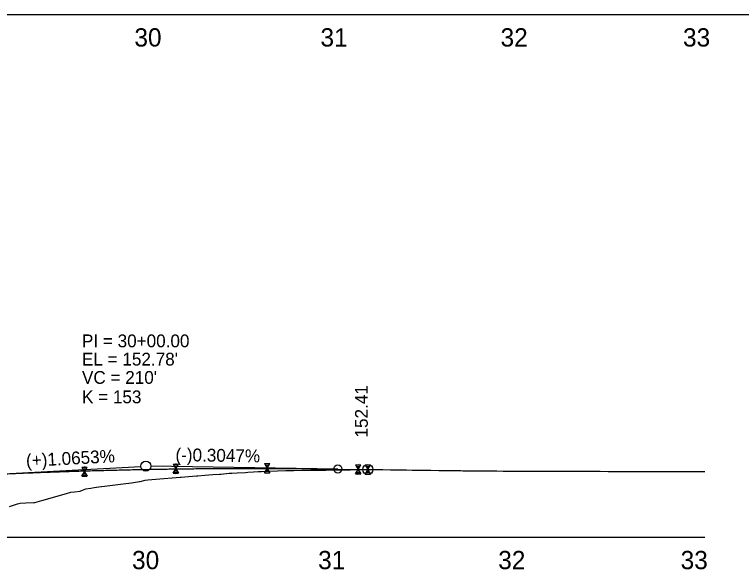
# Model space of a CAD drawing. Extents: x 573468 to 580768, y -57414 to -51768.
# Drawn here: x 575698.2 to 576096, y -53708.9 to -53405.3 of the extents above; entities that cross this region are included whole.
import ezdxf

# ---------------------------------------------------------------- set-up
doc = ezdxf.new("R2010")
doc.units = 0
for name, color, linetype in [('Exist Profile Cell', 7, 'Continuous'), ('Exist Vertical Profile Ground Line', 7, 'Continuous'), ('Exist Vertical Profile Horizontal Axis Label Major', 7, 'Continuous'), ('Pattern 2', 7, 'Continuous'), ('Prop Vertical Profile Curve Label', 7, 'Continuous'), ('Prop Vertical Profile Grade', 7, 'Continuous'), ('Prop Vertical Profile Grade Label', 7, 'Continuous'), ('Prop VPI Label', 7, 'Continuous')]:
    doc.layers.add(name, color=color, linetype=linetype)

msp = doc.modelspace()

# ---------------------------------------------------------------- linework, layer by layer
at = {"layer": 'Exist Profile Cell'}
for p, q in [((573502.62, -53405.32), (576177.52, -53405.32)), ((573531.99, -53691.24), (576075.95, -53691.24))]:
    msp.add_line(p, q, dxfattribs=at)
at = {"layer": 'Exist Vertical Profile Ground Line'}
for points in [[(575731.04, -53666.41), (575734.14, -53665.98), (575735.49, -53665.44), (575737.3, -53664.72), (575739.95, -53664.35), (575741.73, -53664.09), (575744.4, -53663.76), (575748.85, -53663.21), (575753.3, -53662.64), (575757.75, -53662.05), (575762.2, -53661.44), (575766.66, -53660.82), (575766.98, -53660.78), (575769.63, -53660.04), (575771.11, -53659.92), (575775.56, -53659.55), (575780.01, -53659.18), (575784.46, -53658.81), (575788.91, -53658.44), (575789.46, -53658.39), (575793.37, -53658.06), (575797.82, -53657.68), (575798.46, -53657.63), (575802.27, -53657.35), (575806.72, -53657.02), (575810.3, -53656.75), (575811.17, -53656.67), (575815.62, -53656.26), (575817.05, -53656.13), (575820.08, -53655.98), (575824.53, -53655.77), (575825.92, -53655.7), (575828.98, -53655.5), (575831.55, -53655.32), (575833.39, -53655.25), (575837.8, -53655.07), (575842.21, -53654.89), (575846.62, -53654.72), (575847.02, -53654.71), (575847.81, -53654.7), (575851.03, -53654.67), (575855.44, -53654.62), (575859.85, -53654.57), (575864.26, -53654.52), (575868.67, -53654.48), (575870.5, -53654.46), (575872.53, -53654.44), (575873.08, -53654.43), (575875.13, -53654.41), (575877.49, -53654.38), (575881.9, -53654.32), (575886.31, -53654.26), (575890.72, -53654.2), (575891.57, -53654.19), (575895.13, -53654.24), (575899.09, -53654.29), (575899.8, -53654.29), (575903.95, -53654.34), (575908.36, -53654.4), (575909.99, -53654.42), (575912.77, -53654.45), (575915.87, -53654.49), (575917.18, -53654.51), (575921.59, -53654.57), (575926, -53654.63), (575930.41, -53654.69), (575934.82, -53654.75), (575938.81, -53654.8), (575939.23, -53654.8), (575942.49, -53654.83), (575943.64, -53654.85), (575947.11, -53654.89), (575948.05, -53654.9), (575952.46, -53654.93), (575956.87, -53654.97), (575961.28, -53655), (575962.07, -53655.01), (575965.69, -53655.04), (575970.1, -53655.07), (575974.51, -53655.1), (575976.49, -53655.11), (575978.93, -53655.12), (575982.38, -53655.13), (575983.34, -53655.14), (575984.86, -53655.15), (575987.75, -53655.16), (575992.16, -53655.17), (575996.57, -53655.18), (576000.98, -53655.19), (576005.39, -53655.2), (576005.84, -53655.2), (576009.8, -53655.2), (576014.21, -53655.19), (576014.82, -53655.19), (576015.79, -53655.19), (576018.62, -53655.2), (576023.13, -53655.23), (576027.44, -53655.24), (576029.08, -53655.24), (576031.85, -53655.25), (576036.26, -53655.27)], [(576036.26, -53655.27), (576040.67, -53655.29), (576045.08, -53655.3), (576049.49, -53655.32), (576052.49, -53655.33), (576053.9, -53655.34), (576056.55, -53655.35), (576058.31, -53655.34), (576062.72, -53655.33), (576065.23, -53655.33), (576067.13, -53655.33), (576068.52, -53655.33), (576071.54, -53655.32), (576075.95, -53655.3)], [(575695.43, -53674.53), (575699.88, -53673.04), (575701.23, -53672.58), (575704.33, -53672.43), (575708.78, -53672.2), (575709.34, -53672.17), (575713.24, -53671.11), (575717.69, -53669.88), (575722.14, -53668.64), (575726.59, -53667.37), (575728.98, -53666.69), (575731.04, -53666.41)]]:
    msp.add_lwpolyline(points, dxfattribs=at)
at = {"layer": 'Pattern 2'}
for p, q in [((575735.1, -53652.94), (575738.03, -53652.94)), ((575735.1, -53652.94), (575736.57, -53655.44)), ((575736.57, -53655.44), (575738.03, -53652.94)), ((575785.03, -53651.29), (575787.96, -53651.29)), ((575785.03, -53651.29), (575786.5, -53653.79)), ((575785.52, -53652.13), (575787.47, -53652.13)), ((575786.01, -53652.96), (575786.99, -53652.96)), ((575786.5, -53653.79), (575787.96, -53651.29)), ((575834.99, -53650.99), (575837.92, -53650.99)), ((575834.99, -53650.99), (575836.46, -53653.49)), ((575835.48, -53651.83), (575837.43, -53651.83)), ((575835.97, -53652.66), (575836.95, -53652.66)), ((575836.46, -53653.49), (575837.92, -53650.99)), ((575884.88, -53651.64), (575887.81, -53651.64)), ((575884.88, -53651.64), (575886.35, -53654.14)), ((575885.37, -53652.48), (575887.32, -53652.48)), ((575885.86, -53653.31), (575886.84, -53653.31)), ((575886.35, -53654.14), (575887.81, -53651.64)), ((575890.09, -53651.69), (575893.02, -53651.69)), ((575890.09, -53651.69), (575891.56, -53654.19)), ((575890.58, -53652.53), (575892.53, -53652.53)), ((575891.07, -53653.36), (575892.05, -53653.36)), ((575891.56, -53654.19), (575893.02, -53651.69)), ((575735.1, -53657.94), (575736.57, -53655.44)), ((575735.59, -53653.78), (575737.54, -53653.78)), ((575735.59, -53657.11), (575737.54, -53657.11)), ((575736.08, -53654.61), (575737.06, -53654.61)), ((575736.08, -53656.28), (575737.06, -53656.28)), ((575736.57, -53655.44), (575738.03, -53657.94)), ((575785.03, -53656.29), (575786.5, -53653.79)), ((575785.03, -53656.29), (575787.96, -53656.29)), ((575785.52, -53655.46), (575787.47, -53655.46)), ((575786.01, -53654.63), (575786.99, -53654.63)), ((575786.5, -53653.79), (575787.96, -53656.29)), ((575834.99, -53655.99), (575836.46, -53653.49)), ((575834.99, -53655.99), (575837.92, -53655.99)), ((575835.48, -53655.16), (575837.43, -53655.16)), ((575835.97, -53654.33), (575836.95, -53654.33)), ((575836.46, -53653.49), (575837.92, -53655.99)), ((575884.88, -53656.64), (575886.35, -53654.14)), ((575884.88, -53656.64), (575887.81, -53656.64)), ((575885.37, -53655.81), (575887.32, -53655.81)), ((575885.86, -53654.98), (575886.84, -53654.98)), ((575886.35, -53654.14), (575887.81, -53656.64)), ((575890.09, -53656.69), (575891.56, -53654.19)), ((575890.09, -53656.69), (575893.02, -53656.69)), ((575890.58, -53655.86), (575892.53, -53655.86)), ((575891.07, -53655.03), (575892.05, -53655.03)), ((575891.56, -53654.19), (575893.02, -53656.69)), ((575735.1, -53657.94), (575738.03, -53657.94))]:
    msp.add_line(p, q, dxfattribs=at)
at = {"layer": 'Prop Vertical Profile Curve Label'}
msp.add_circle((575875.13, -53653.94), 2.25, dxfattribs=at)
at = {"layer": 'Prop Vertical Profile Grade'}
msp.add_line((575875.13, -53653.94), (575891.56, -53654.19), dxfattribs=at)
msp.add_spline([(575665.13, -53657.94), (575669.33, -53657.72), (575673.53, -53657.5), (575677.73, -53657.29), (575681.93, -53657.09), (575686.13, -53656.89), (575690.33, -53656.7), (575694.53, -53656.51), (575698.73, -53656.33), (575702.93, -53656.16), (575707.13, -53655.99), (575711.33, -53655.82), (575715.53, -53655.67), (575719.73, -53655.51), (575723.93, -53655.37), (575728.13, -53655.23), (575732.33, -53655.09), (575736.53, -53654.96), (575740.73, -53654.84), (575744.93, -53654.72), (575749.13, -53654.61), (575753.33, -53654.51), (575757.53, -53654.41), (575761.73, -53654.31), (575765.93, -53654.22), (575770.13, -53654.14), (575774.33, -53654.06), (575778.53, -53653.99), (575782.73, -53653.93), (575786.93, -53653.87), (575791.13, -53653.81), (575795.33, -53653.77), (575799.53, -53653.72), (575803.73, -53653.69), (575807.93, -53653.66), (575812.13, -53653.63), (575816.33, -53653.61), (575820.53, -53653.6), (575824.73, -53653.59), (575828.93, -53653.59), (575833.13, -53653.59), (575837.33, -53653.6), (575841.53, -53653.62), (575845.73, -53653.64), (575849.93, -53653.66), (575854.13, -53653.7), (575858.33, -53653.73), (575862.53, -53653.78), (575866.73, -53653.83), (575870.93, -53653.88), (575875.13, -53653.94)], degree=3, dxfattribs=at)
at = {"layer": 'Prop VPI Label'}
for p, q in [((575665.13, -53657.94), (575767.39, -53652.49)), ((575875.13, -53653.94), (575772.88, -53652.39))]:
    msp.add_line(p, q, dxfattribs=at)
for centre in [(575770.13, -53652.34), (575891.56, -53654.19)]:
    msp.add_circle(centre, 2.75, dxfattribs=at)

# ---------------------------------------------------------------- texts
at = {"layer": 'Exist Vertical Profile Horizontal Axis Label Major'}
for s, p in [('30', (575763.81, -53422.82)), ('31', (575865.65, -53422.82)), ('32', (575964.2, -53422.82)), ('33', (576064.04, -53422.82)), ('30', (575762.52, -53708.74)), ('31', (575864.36, -53708.74)), ('32', (575962.91, -53708.74)), ('33', (576062.74, -53708.74))]:
    msp.add_text(s, height=10, dxfattribs=at).set_placement(p)
at = {"layer": 'Pattern 2'}
for s, p in [('6"', (575736.45, -53652.84)), ('6"', (575786.38, -53651.19)), ('6"', (575836.34, -53650.89)), ('6"', (575886.23, -53651.54)), ('6"', (575891.44, -53651.59)), ('-6"', (575785.92, -53656.9)), ('-6"', (575835.88, -53656.6)), ('-6"', (575885.77, -53657.25)), ('-6"', (575890.98, -53657.3)), ('-6"', (575735.99, -53658.55))]:
    msp.add_text(s, height=0.5, rotation=360, dxfattribs=at).set_placement(p)
at = {"layer": 'Prop Vertical Profile Curve Label'}
for s, p in [("VC = 210'", (575735.13, -53607.34)), ('K = 153', (575735.13, -53617.97))]:
    msp.add_text(s, height=7, dxfattribs=at).set_placement(p)
at = {"layer": 'Prop Vertical Profile Grade Label'}
for s, rotation, p in [('(+)1.0653%', 3.0489, (575704.68, -53652.83)), ('(-)0.3047%', 359.1272, (575786.25, -53649.59))]:
    msp.add_text(s, height=7, rotation=rotation, dxfattribs=at).set_placement(p)
at = {"layer": 'Prop VPI Label'}
for s, p in [('PI = 30+00.00', (575735.13, -53587.34)), ("EL = 152.78'", (575735.13, -53597.34))]:
    msp.add_text(s, height=7, dxfattribs=at).set_placement(p)
msp.add_text('152.41', height=7, rotation=90, dxfattribs=at).set_placement((575891.56, -53636.69))

doc.saveas('drawing.dxf')
